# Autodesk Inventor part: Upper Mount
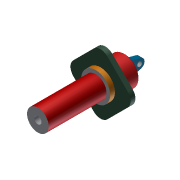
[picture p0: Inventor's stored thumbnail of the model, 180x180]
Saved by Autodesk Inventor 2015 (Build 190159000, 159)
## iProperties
Created: 2020-09
Part Number: Upper Mount
Material: 一般
Document SubType Name: Modeling
Designer: 徐冠倫
Mass: 412.012 g
Surface Area: 582.449 cm^2
Volume: 412.012 cm^3
Density: 1 g/cm^3
Appearance: 預設
Author: 徐冠倫
Author: IANNIAN
Title: D:\Desktop\OCW-Computer-Aided Engineering Drawing\OCW_Topic 06：組合圖與機構模擬(進階)\Shock Absorber\Upper-STP.stp
Creation Date: 2020-08-21
Sending System: Autodesk Inventor 2020
Preprocessor: ST-DEVELOPER v18
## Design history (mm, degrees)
node "Upper-STP1"
body "Solid1"
node "Base1"
